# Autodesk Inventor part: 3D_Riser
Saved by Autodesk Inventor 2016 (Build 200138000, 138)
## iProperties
Created: 2016-03
Part Number: 3D_Riser
Material: Generic
Document SubType Name: Modeling
Designer: bongo_000
Density: 1 g/cm^3
Appearance: Default
Author: bongo_000
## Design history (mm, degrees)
feature "SOLID1"
body "Solid1"
